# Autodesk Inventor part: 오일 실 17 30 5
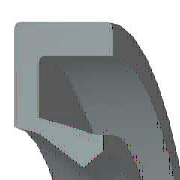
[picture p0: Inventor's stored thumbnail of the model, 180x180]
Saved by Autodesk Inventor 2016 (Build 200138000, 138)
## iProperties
IsCustomPart: 1
Created: 2012-02
Part Number: 오일 실 17 30 5
Material: 고무
Description: 오일 실 - 비스프링, 조립 GA
Document SubType Name: Modeling
Standard: JIS B 2402
Designer: mduedu
Standards Organization: JIS
Language: ko-KR
Size Designation: 17 30 5 A
Categories: <MemberInstance><Categories><Category DisplayName="샤프트 부품" InternalName="7f7aeb1f-a693-4053-b835-cee3144e0d98" Mnemonic="SHFT"><Category DisplayName="실링" Intern
Density: 0.93 g/cm^3
Appearance: Rubber-Black
Mass: 1.39335 g
Surface Area: 19.422 cm^2
Volume: 1.49822 cm^3
Author: mduedu
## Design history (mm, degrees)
body "Solid1"
revolve "회전1" stored, may be unused: angle "d27" = 360 deg
fillet "모깎기1" dims "d28" = 0.25 (= 0.05 x b)
sketch "스케치2"
  geometry: L1 (10.636, -3.75)-(11.286, -5); L2 (9.769, -3.438)-(10.636, -3.75); L3 (8.5, -1.375)-(9.769, -3.438); L4 (9.5, -0.75)-(8.5, -1.375); L5 (12.4, -4.375)-(9.5, -0.75); L6 (12.4, -0.25)-(12.4, -4.375); L7 (13.7, -0.25)-(12.4, -0.25); L8 (13.7, 0)-(13.7, -0.25); L9 (15, 0)-(13.7, 0); L10 (15, -5)-(15, 0); L11 (11.286, -5)-(15, -5); L12 (0, -9.6)-(0, 1.6) reference; L13 (28, 0)-(14, 0) reference
  constraints: 22 end point, 3 horizontal, 3 vertical
  dimensions: "d2" = 5 distance of L10.start L9.start (= b); "d4" = 1.3 distance of L9.start L8.start (= 0.1 x dd - 0.1 x Diam); "d6" = 0.25 distance of L8.start L7.start (= 0.05 x b); "d8" = 1 horizontal distance of L4.start L3.start (= 0.0769231 x dd - 0.0769231 x Diam); "d10" = 0.625 vertical distance of L5.start L10.start (= 0.125 x b); "d12" = 1.3 distance of L7.start L6.start (= 0.1 x dd - 0.1 x Diam); "d14" = 0.5 vertical distance of L4.start L6.start (= 0.1 x b); "d16" = 3.71429 distance of L1.end L10.start (= 0.285714 x dd - 0.285714 x Diam); "d18" = 0.65 horizontal distance of L1.start L1.end (= 0.05 x dd - 0.05 x Diam); "d20" = 0.625 vertical distance of L4.start L3.start (= 0.125 x b); "d22" = 1.25 vertical distance of L1.start L1.end (= 0.25 x b); "d24" = 0.86667 horizontal distance of L2.start L1.start (= 0.0666667 x dd - 0.0666667 x Diam); "d26" = 0.3125 vertical distance of L2.start L1.start (= 0.0625 x b); "d29" = 0 distance between parallel lines of L13 L9; "d30" = 8.5 distance from line of L3.start L12 (= 0.5 x Diam); "d31" = 15 distance between parallel lines of L12 L10 (= 0.5 x dd)
other parameters: "Diam" = 17 [user parameter; used in 7 equation terms], "b" = 5 [user parameter; used in 8 equation terms], "d1" = 8 (derived), "d3" = 2 (derived), "d5" = 0.4 (derived), "d7" = 1.53846 (derived), "d9" = 1 (derived), "d11" = 2 (derived), "d13" = 0.8 (derived), "d15" = 5.71429 (derived), "d17" = 1 (derived), "d19" = 1 (derived), "d21" = 2 (derived), "d23" = 1.33333 (derived), "d25" = 0.5 (derived), "d32" = 0
